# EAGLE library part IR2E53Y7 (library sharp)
Auto-brightness control with ambient light sensor 18 sets of 6 LEDs in series. Source: http://document.sharpsma.com/files/IR2E53Y7.pdf
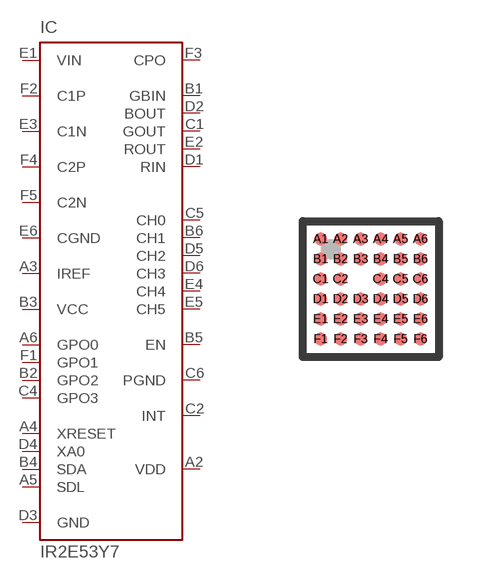
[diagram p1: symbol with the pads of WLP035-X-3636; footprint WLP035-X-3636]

Designator prefix IC

## IR2E53Y7 (OC_FARNELL: unknown; OC_NEWARK: unknown)  [WLP035-X-3636]
A2  VDD  pwr
A3  IREF  in
A4  XRESET  in
A5  SDL  in
A6  GPO0  in
B1  GBIN  in
B2  GPO2  in
B3  VCC  pwr
B4  SDA  in
B5  EN  in
B6  CH1  out
C1  GOUT  out
C2  INT  pas
C4  GPO3  in
C5  CH0  out
C6  PGND  pas
D1  RIN  out
D2  BOUT  out
D3  GND  pwr
D4  XA0  in
D5  CH2  out
D6  CH3  out
E1  VIN  in
E2  ROUT  out
E3  C1N  pas
E4  CH4  out
E5  CH5  out
E6  CGND  pwr
F1  GPO1  in
F2  C1P  pas
F3  CPO  pas
F4  C2P  pas
F5  C2N  pas

## Footprint WLP035-X-3636 (pad centres in mm)
Ball Grid Array WLP035-X-3636 35-pin WL-CSP package (3.57 x 3.57mm) Source: http://document.sharpsma.com/files/IR2E53Y7.pdf
smd 0.33 x 0.33: A1 -1.25,1.25; A2 -0.75,1.25; A3 -0.25,1.25; A4 0.25,1.25; A5 0.75,1.25; A6 1.25,1.25; B1 -1.25,0.75; B2 -0.75,0.75; B3 -0.25,0.75; B4 0.25,0.75; B5 0.75,0.75; B6 1.25,0.75; C1 -1.25,0.25; C2 -0.75,0.25; C4 0.25,0.25; C5 0.75,0.25; C6 1.25,0.25; D1 -1.25,-0.25; D2 -0.75,-0.25; D3 -0.25,-0.25; D4 0.25,-0.25; D5 0.75,-0.25; D6 1.25,-0.25; E1 -1.25,-0.75; E2 -0.75,-0.75; E3 -0.25,-0.75; E4 0.25,-0.75; E5 0.75,-0.75; E6 1.25,-0.75; F1 -1.25,-1.25; F2 -0.75,-1.25; F3 -0.25,-1.25; F4 0.25,-1.25; F5 0.75,-1.25; F6 1.25,-1.25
